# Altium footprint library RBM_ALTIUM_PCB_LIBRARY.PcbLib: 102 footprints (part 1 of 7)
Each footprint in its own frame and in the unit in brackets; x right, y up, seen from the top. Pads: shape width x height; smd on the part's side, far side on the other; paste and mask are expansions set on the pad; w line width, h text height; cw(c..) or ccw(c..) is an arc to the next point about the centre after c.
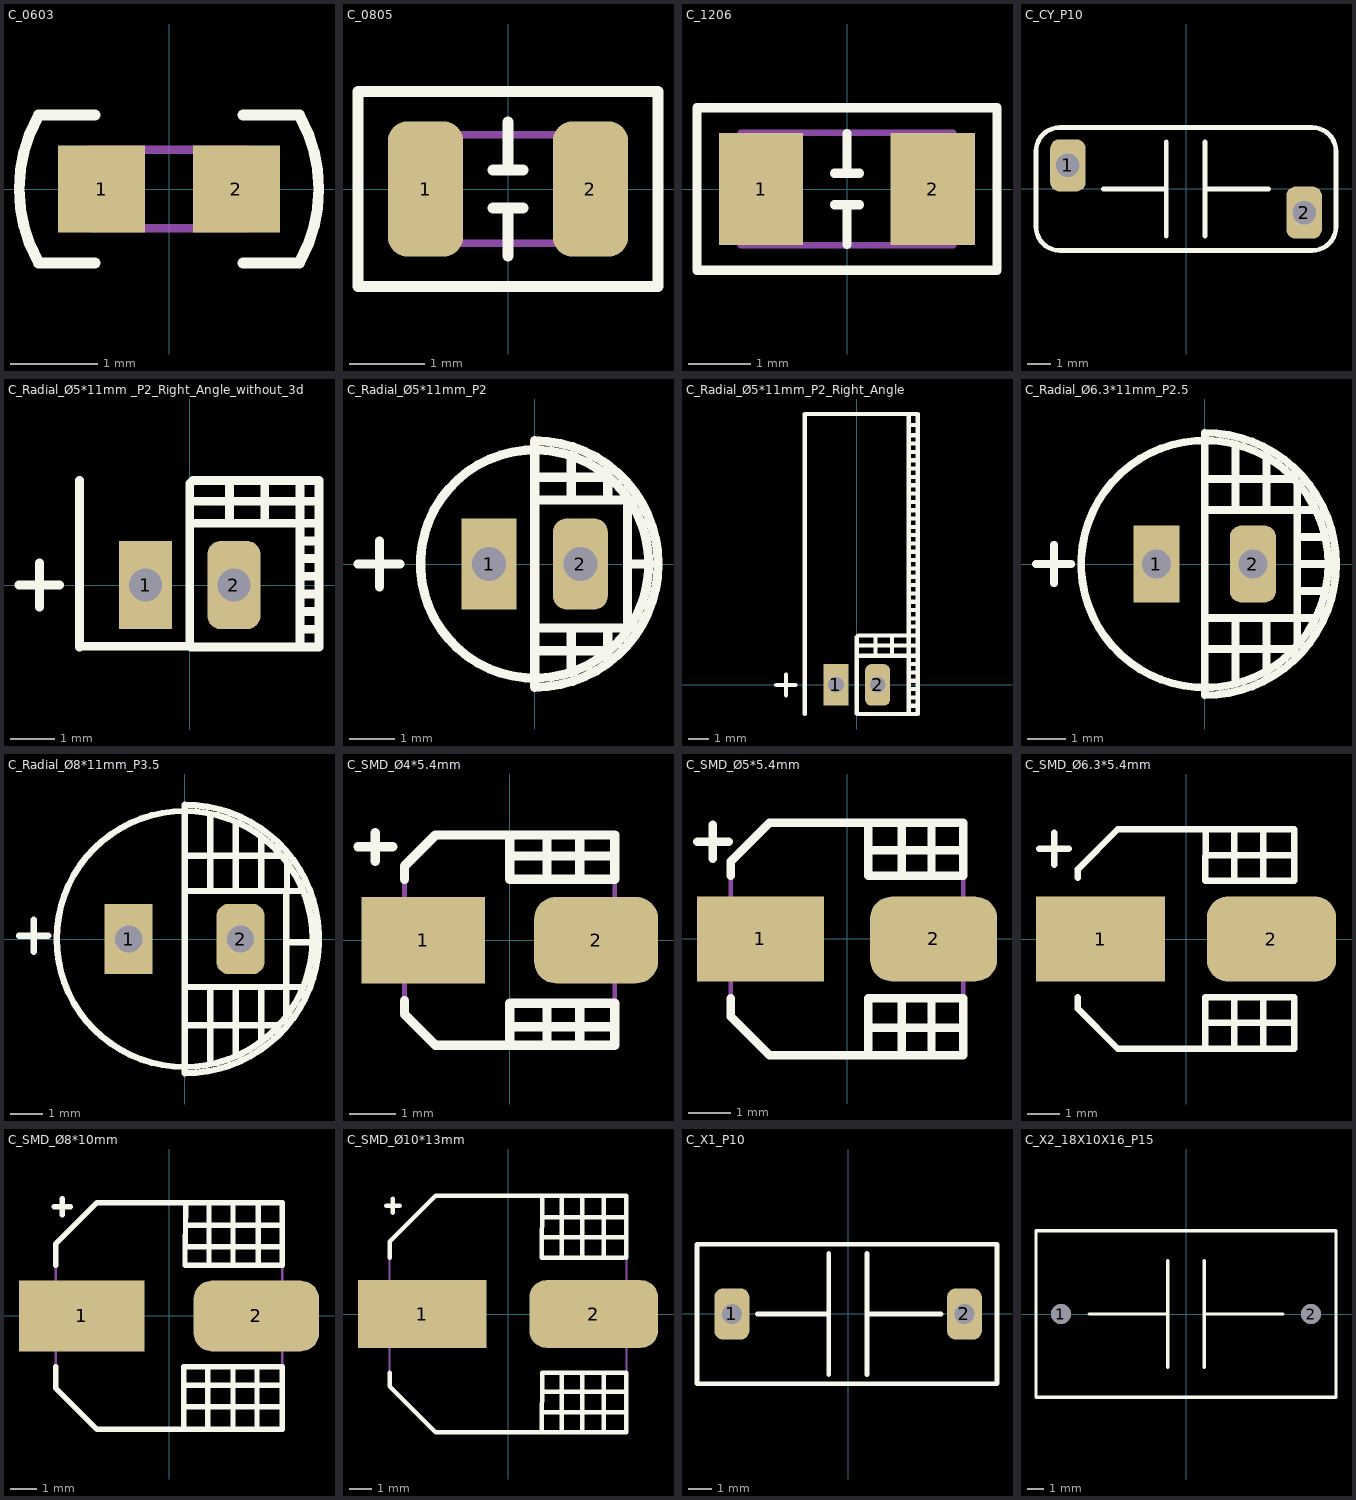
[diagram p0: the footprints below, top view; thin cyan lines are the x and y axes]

## C_0603 [mm] "0603 Multilayer Ceramic Capacitors MLCC - SMD/SMT RoHS"
height 0.87
pads (2):
  rect 1x1 smd: 1(-0.775,0) 2(0.775,0)
Top Overlay:
  lines w0.125: -1.508,-0.836 cw(c0.001,0) -1.508,0.836 ; -1.5,-0.85 -0.85,-0.85 ; -1.5,0.85 -0.85,0.85 ; 0.85,-0.85 1.5,-0.85 ; 0.85,0.85 1.5,0.85 ; 1.508,-0.836 ccw(c-0.001,0) 1.508,0.836
Assembly Top:
  lines w0.1: -0.9,-0.45 0.9,-0.45 0.9,0.45 -0.9,0.45 -0.9,-0.45
3D body "Chip2PinSM127P600-8N.step": height 0.87, standoff 0, extent -0.85,-0.45 0.85,0.45

## C_0805 [mm]
height 1
pads (2):
  rrect50% 1x1.8 smd: 1(-1.1,0) 2(1.1,0)
Top Overlay:
  lines w0.15: -0.2,-0.254 0.2,-0.254 ; -0.2,0.254 0.2,0.254 ; 0,-0.889 0,-0.254 ; 0,0.254 0,0.889 ; -2,-1.3 -2,1.3 2,1.3 2,-1.3 -2,-1.3
Mechanical 13:
  lines w0.1: -1.1,-0.725 -1.1,0.725 1.1,0.725 1.1,-0.725 -1.1,-0.725
3D body "C_0805.step": height 1, standoff 0, extent -1.1,-0.725 1.1,0.725

## C_1206 [mm] "NM1206B104K451CEGN; 100nF ±10% 450V X7R 1206 Multilayer Ceramic Capacitors MLCC - SMD/SMT RoHS"
height 1.8
pads (2):
  rect 1.35x1.8 smd: 1(-1.375,0) 2(1.375,0)
Top Overlay:
  lines w0.15: -0.2,-0.254 0.2,-0.254 ; -0.2,0.254 0.2,0.254 ; 0,-0.889 0,-0.254 ; 0,0.254 0,0.889 ; -2.4,-1.3 2.4,-1.3 2.4,1.3 -2.4,1.3 -2.4,-1.3
Assembly Top:
  lines w0.1: -1.7,-0.9 -1.7,0.9 1.7,0.9 1.7,-0.9 -1.7,-0.9
3D body "Chip2PinSM127P600-8N.step": height 1.8, standoff 0, extent -1.7,-0.9 1.7,0.9

## C_CY_P10 [mm] "CY1222ME1IEF46X0A2; 2.2nF ±20% 400VAC 10 Through Hole,P=10mm Suppression Capacitors RoHS"
pads (2):
  rrect50% 1.5x2.2 hole 1: 1(-5,1) 2(5,-1)
Top Overlay:
  lines w0.2: -3.5,-0.001 -0.84,0 ; -0.84,-1.999 -0.84,1.999 ; 0.807,-1.999 0.807,1.999 ; 0.807,0 3.5,0 ; -6.35,-1.6 ccw(c-5.35,-1.6) -5.35,-2.6 5.35,-2.6 ccw(c5.35,-1.6) 6.35,-1.6 6.35,1.6 ccw(c5.35,1.6) 5.35,2.6 -5.35,2.6 ccw(c-5.35,1.6) -6.35,1.6 -6.35,-1.6
3D body "CY-2.2nF-400V.STEP": height 9.75, standoff -1.5, extent -5.658,-2.193 5.658,2.193

## C_Radial_Ø5*11mm _P2_Right_Angle_without_3d [mm]
pads (2):
  rect 1.2x2 hole 0.75: 1(-1,0)
  rrect50% 1.2x2 hole 0.75: 2(1,0)
Top Overlay:
  lines w0.2: -3.87,0.002 -2.954,0.002 ; -3.403,-0.498 -3.403,0.502 ; -2.5,2.369 -2.5,-1.4 cw(c-2.487,-1.4) -2.487,-1.387 0.013,-1.387 ; 0.1,1.4 2.929,1.4 ; 0.1,1.9 2.9,1.9 ; 0.9,1.4 0.9,2.369 ; 1.7,1.5 1.7,2.3 ; 2.5,2.369 2.5,-1.4 0.025,-1.4 0,-1.375 0,2.3 ; 2.518,-0.2 2.896,-0.2 ; 2.518,0.2 2.882,0.2 ; 2.518,0.6 2.896,0.6 ; 2.518,1 2.882,1 ; 2.551,-1.4 2.929,-1.4 2.929,2.369 0.069,2.369 0.001,2.3 ; 2.551,-1 2.929,-1 ; 2.551,-0.6 2.914,-0.6 ; 0,2.3 0.001,2.3

## C_Radial_Ø5*11mm_P2 [mm]
pads (2):
  rect 1.2x2 hole 0.75: 1(-1,0)
  rrect50% 1.2x2 hole 0.75: 2(1,0)
Top Overlay:
  lines w0.2: -3.87,0.002 -2.954,0.002 ; -3.403,-0.498 -3.403,0.502 ; 0,-1.4 2.029,-1.4 2.029,1.4 0,1.4 ; 0.1,-1.9 1.6,-1.9 ; 0.1,1.9 1.6,1.9 ; 0.8,-2.369 0.8,-1.4 ; 0.8,1.4 0.8,2.369 ; 1.6,-1.921 1.6,-1.4 ; 1.6,1.5 1.6,1.921 ; 2.092,0 2.5,0 ; 2.5,0 ccw(c0,0) 2.5,0 ; 0,-2.7 ccw(c0,0) 0,2.7 0,-2.7
3D body "User Library-Cap electro 5x11x2mm.step": height 11.53, standoff -3.27, extent -2.525,-2.525 2.526,2.525

## C_Radial_Ø5*11mm_P2_Right_Angle [mm]
pads (2):
  rect 1.2x2 hole 0.75: 1(-1,0)
  rrect50% 1.2x2 hole 0.75: 2(1,0)
Top Overlay:
  lines w0.2: -3.87,0.002 -2.954,0.002 ; -3.403,-0.498 -3.403,0.502 ; -2.5,-1.4 -2.5,13.026 2.5,13.026 ; 0.1,1.4 2.929,1.4 ; 0.1,1.9 2.9,1.9 ; 0.9,1.4 0.9,2.369 ; 1.7,1.5 1.7,2.3 ; 2.518,-0.2 2.896,-0.2 ; 2.518,0.2 2.882,0.2 ; 2.518,0.6 2.896,0.6 ; 2.518,1 2.882,1 ; 2.518,3.6 2.896,3.6 ; 2.518,4 2.882,4 ; 2.518,4.4 2.896,4.4 ; 2.518,4.8 2.882,4.8 ; 2.518,6 2.896,6 ; 2.518,6.4 2.882,6.4 ; 2.518,6.8 2.896,6.8 ; 2.518,7.2 2.882,7.2 ; 2.518,8.4 2.896,8.4 ; 2.518,8.8 2.882,8.8 ; 2.518,9.2 2.896,9.2 ; 2.518,9.6 2.882,9.6 ; 2.518,10.8 2.896,10.8 ; 2.518,11.2 2.882,11.2 ; 2.518,11.6 2.896,11.6 ; 2.518,12 2.882,12 ; 2.518,12.5 2.882,12.5 ; 2.551,-1.4 2.929,-1.4 2.929,13.026 2.5,13.026 ; 2.551,-1 2.929,-1 ; 2.551,-0.6 2.914,-0.6 ; 2.551,2.8 2.929,2.8 ; 2.551,3.2 2.914,3.2 ; 2.551,5.2 2.929,5.2 ; 2.551,5.6 2.914,5.6 ; 2.551,7.6 2.929,7.6 ; 2.551,8 2.914,8 ; 2.551,10 2.929,10 ; 2.551,10.4 2.914,10.4 ; 2.929,2.369 0.069,2.369 0.001,2.3 ; 0,2.3 0.001,2.3 ; 0,2.3 0,-1.375 0.025,-1.4 2.5,-1.4 2.5,13.026
3D body "User Library-Cap electro 5x11x2mm RA.step": height 5.53, standoff -3, extent -2.5,-0.295 2.551,13.026

## C_Radial_Ø6.3*11mm_P2.5 [mm]
pads (2):
  rect 1.2x2 hole 0.75: 1(-1.25,0)
  rrect50% 1.2x2 hole 0.75: 2(1.25,0)
Top Overlay:
  lines w0.2: -4.37,0.002 -3.454,0.002 ; -3.903,-0.498 -3.903,0.502 ; 0,-1.4 2.8,-1.4 ; 0,1.4 2.8,1.4 ; 0.1,-2.2 2.3,-2.2 ; 0.1,2.2 2.3,2.2 ; 0.8,-3.1 0.8,-1.4 ; 0.8,1.4 0.8,3.1 ; 1.6,-2.7 1.6,-1.4 ; 1.6,1.5 1.6,2.7 ; 2.4,-2.1 2.4,2.1 ; 2.4,-0.7 3.1,-0.7 ; 2.4,0 3.2,0 ; 2.4,0.7 3.1,0.7 ; 3.2,0 ccw(c0,0) 3.2,0 ; 0,-3.401 ccw(c0,0) 0,3.402 0,-3.401
3D body "User Library-Cap electro 6_3x11x2_5mm.step": height 11.53, standoff -3.01, extent -3.175,-3.175 3.176,3.176

## C_Radial_Ø8*11mm_P3.5 [mm]
pads (2):
  rect 1.5x2.2 hole 0.85: 1(-1.75,0)
  rrect50% 1.5x2.2 hole 0.85: 2(1.75,0)
Top Overlay:
  circle w0.2: c0,0 r4
  lines w0.1: 0,0 0,4
  lines w0.2: -5.178,0.1 -4.262,0.1 ; -4.711,-0.4 -4.711,0.6 ; 0,-2.7 2.9,-2.7 ; 0,-1.5 3.7,-1.5 ; 0,1.5 3.7,1.5 ; 0,2.6 3,2.6 ; 0.8,-3.9 0.8,-1.5 ; 0.8,1.5 0.8,3.9 ; 1.6,-3.6 1.6,-1.5 ; 1.6,1.5 1.6,3.6 ; 2.4,-3.2 2.4,-1.6 ; 2.4,1.5 2.4,3.2 ; 3.176,-2.4 3.176,-1.524 3.176,1.476 3.2,1.5 3.2,2.4 ; 3.2,-0.1 3.9,-0.1 ; 0,-4.2 ccw(c0,0) 0,4.2 0,-4.2
3D body "User Library-Cap electro 8x11_5x3_5mm.step": height 12.03, standoff -3.48, extent -4.025,-4.025 4.026,4.026

## C_SMD_Ø4*5.4mm [mm]
height 5.8
pads (2):
  rect 2.65x1.85 smd: 1(-1.85,0)
  rrect50% 2.65x1.85 smd: 2(1.85,0)
Top Overlay:
  lines w0.2: -3.245,2 -2.5,2 ; -2.878,1.687 -2.878,2.3 ; -2.25,-1.3 -2.25,-1.587 -1.587,-2.25 2.25,-2.25 2.25,-1.35 0,-1.35 0,-2.163 ; -2.25,1.3 -2.25,1.587 -1.587,2.25 2.25,2.25 2.25,1.3 0,1.3 ; 0,-1.85 2.25,-1.85 ; 0,1.8 2.25,1.8 ; 0,1.9 0,1.3 ; 0,2.25 0,1.3 ; 0.8,-2.175 0.8,-1.35 ; 0.8,1.3 0.8,2.25 ; 1.5,-2.175 1.5,-1.35 ; 1.5,1.3 1.5,2.25
Mechanical 13:
  lines w0.1: -2.25,-1.587 -1.587,-2.25 2.25,-2.25 2.25,2.25 -1.587,2.25 -2.25,1.587 -2.25,-1.587
3D body "CAPAE4643X58M.step": height 5.8, standoff 0, extent -2.275,-2.25 2.275,2.25

## C_SMD_Ø5*5.4mm [mm]
height 5.8
pads (2):
  rect 3x2 smd: 1(-2.05,0)
  rrect50% 3x2 smd: 2(2.05,0)
Top Overlay:
  lines w0.2: -3.545,2.3 -2.8,2.3 ; -3.178,1.9 -3.178,2.7 ; -2.75,-1.4 -2.75,-1.837 -1.838,-2.75 2.75,-2.75 2.75,-1.4 0.5,-1.4 ; -2.75,1.5 -2.75,1.837 -1.838,2.75 2.75,2.75 2.75,1.5 0.5,1.5 ; 0.5,-2.75 0.5,-1.4 ; 1.3,-1.4 1.3,-2.75 2,-2.75 2,-1.4 ; 1.3,1.5 1.3,2.75 0.5,2.75 0.5,1.5 ; 2,1.5 2,2.75 ; 2.75,-2.1 0.5,-2.1 0.5,-1.4 ; 2.75,2.1 0.5,2.1 0.5,1.5
Mechanical 13:
  lines w0.1: -2.75,-1.837 -2.75,1.837 -1.838,2.75 2.75,2.75 2.75,-2.75 -1.838,-2.75 -2.75,-1.837
3D body "CAPAE5653X58M.step": height 5.8, standoff 0, extent -2.775,-2.75 2.775,2.75

## C_SMD_Ø6.3*5.4mm [mm] "SMD 6.3x5.4mm Aluminum Electrolytic Capacitors - SMD RoHS"
height 6
pads (2):
  rect 4x2.65 smd: 1(-2.65,0)
  rrect50% 4x2.65 smd: 2(2.65,0)
Top Overlay:
  lines w0.2: -4.545,2.8 -3.629,2.8 ; -4.078,2.3 -4.078,3.3 ; -3.35,-1.8 -3.35,-2.163 -2.112,-3.4 3.35,-3.4 3.35,-1.8 0.6,-1.8 0.6,-3.4 ; -3.35,1.9 -3.35,2.163 -2.112,3.4 3.35,3.4 3.35,1.8 0.602,1.8 0.619,3.4 ; 0.6,-2.6 3.35,-2.6 ; 0.61,2.6 3.35,2.6 ; 1.5,-3.3 1.5,-1.8 ; 1.5,1.9 1.5,3.4 ; 2.4,-3.4 2.4,-1.8 ; 2.4,1.9 2.4,3.4
3D body: height 5.8, standoff 0, extent -3.4,-3.4 3.4,3.4
3D body: height 1.94, standoff 0, extent -3.4,-3.4 3.4,3.4

## C_SMD_Ø8*10mm [mm] "VKMD1002G4R7MV; 4.7uF ±20% 400V SMD,8x10mm Aluminum Electrolytic Capacitors - SMD RoHS"
height 10.5
pads (2):
  rect 4.7x2.65 smd: 1(-3.275,0)
  rrect50% 4.7x2.65 smd: 2(3.275,0)
Top Overlay:
  lines w0.2: -4.3,4.1 -3.7,4.1 ; -4.25,-1.9 -4.25,-2.7 -2.7,-4.25 4.25,-4.25 4.25,-1.9 0.55,-1.9 0.55,-4.25 ; -4.25,1.9 -4.25,2.7 -2.7,4.25 4.25,4.25 4.25,1.9 0.603,1.9 0.628,4.252 ; -4,3.8 -4,4.4 ; 0.55,-3.4 4.181,-3.4 ; 0.55,-2.6 4.19,-2.6 ; 0.61,2.6 4.25,2.6 ; 0.619,3.4 4.25,3.4 ; 1.45,-4.2 1.45,-2 ; 1.5,1.9 1.5,4.25 ; 2.4,-4.2 2.4,-2 ; 2.4,1.9 2.4,4.25 ; 3.3,-4.25 3.3,-1.9 ; 3.35,2 3.35,4.25
Assembly Top:
  lines w0.1: -4.25,-2.7 -2.7,-4.25 4.25,-4.25 4.25,4.25 -2.7,4.25 -4.25,2.7 -4.25,-2.7
3D body "CAPAE9083X105M.step": height 10.5, standoff 0, extent -4.5,-4.25 4.5,4.25

## C_SMD_Ø10*13mm [mm] "VKME1302W6R8MV; 6.8uF ±20% 450V SMD,10x13mm Aluminum Electrolytic Capacitors - SMD RoHS"
height 13.5
pads (2):
  rect 5.7x3 smd: 1(-3.8,0)
  rrect50% 5.7x3 smd: 2(3.8,0)
Top Overlay:
  lines w0.2: -5.4,4.8 -4.8,4.8 ; -5.25,-2.598 -5.25,-3.2 -3.2,-5.25 5.25,-5.25 5.25,-2.598 ; -5.25,2.5 -5.25,3.2 -3.2,5.25 5.25,5.25 5.25,2.5 ; -5.1,4.5 -5.1,5.1 ; 1.49,-5.25 1.517,-2.598 5.167,-2.598 ; 1.5,-4.35 5.14,-4.35 ; 1.5,3.4 5.14,3.4 ; 1.508,-3.45 5.14,-3.45 ; 1.508,4.3 5.14,4.3 ; 1.517,5.152 1.49,2.5 5.14,2.5 ; 2.39,-5.25 2.39,-2.6 ; 2.39,2.5 2.39,5.15 ; 3.29,-5.25 3.29,-2.6 ; 3.29,2.5 3.29,5.15 ; 4.24,-5.25 4.24,-2.6 ; 4.24,2.5 4.24,5.15
Assembly Top:
  lines w0.1: -5.25,-3.2 -3.2,-5.25 5.25,-5.25 5.25,5.25 -3.2,5.25 -5.25,3.2 -5.25,-3.2
3D body "CAPAE110103X135M.step": height 13.5, standoff 0, extent -5.5,-5.25 5.5,5.25

## C_X1_P10 [mm]
pads (2):
  rrect50% 1.5x2.2 hole 0.85: 1(-5,0) 2(5,0)
Top Overlay:
  lines w0.2: -3.9,-0.001 -0.84,0 ; -0.84,-2.6 -0.84,2.6 ; 0.807,-2.6 0.807,2.6 ; 0.807,0 4,0 ; -6.5,-3 -6.5,3 6.4,3 6.4,-3 -6.5,-3
3D body: height 11.89, standoff 0.68, extent -6.414,-2.921 6.35,2.921
3D body: height 1.5, standoff -2, extent -5.297,-0.254 -4.699,0.345
3D body: height 1.5, standoff -2, extent 4.699,-0.254 5.297,0.345

## C_X2_18X10X16_P15 [mm] "STE(Songtian Elec) X2P2474KQ1B0180160100ES0"
pads (2):
  round 1.2 / inner rrect50% 2x3 / far side rrect50% 2x3 hole 1.2: 1(-7.5,0) 2(7.5,0)
Top Overlay:
  lines w0.2: -5.8,0 -1.1,0 ; -1.1,-3.2 -1.1,3.2 ; 1.1,-3.2 1.1,3.2 ; 1.1,0 5.8,0 ; -9,-5 -9,5 9,5 9,-5 -9,-5
3D body: height 3, standoff -2, extent 7.103,-0.399 7.9,0.399
3D body: height 3, standoff -2, extent -7.898,-0.399 -7.102,0.399
3D body: height 16, standoff 0.2, extent -9,-5 9,5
